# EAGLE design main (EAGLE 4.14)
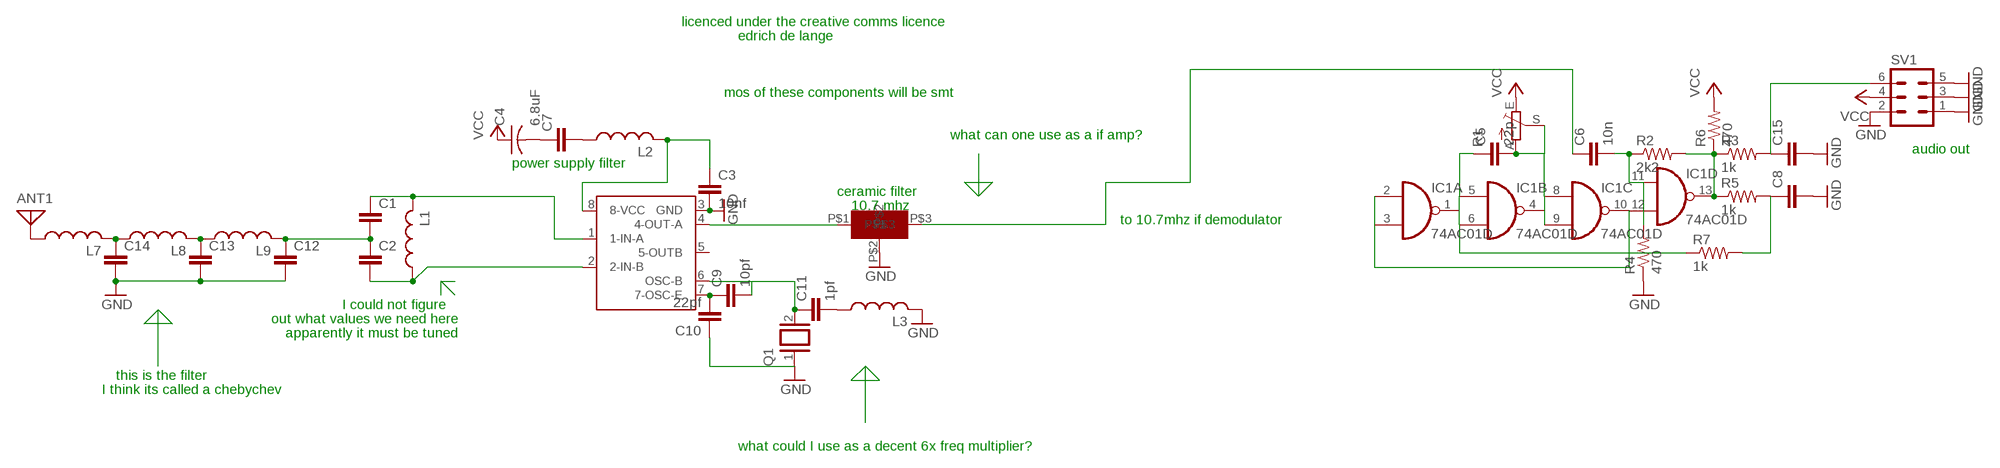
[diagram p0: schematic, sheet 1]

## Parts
ANT1  ANTENNA  [PAD-01]
C1  C-EUC1206K  [C1206K]
C2  C-EUC1206K  [C1206K]
C3  10nf  C-EUC1206K  [C1206K]
C4  6.8uF  CAP-2,5  [C-2,5]
C5  22p  C-EUC1206K  [C1206K]
C6  10n  C-EUC1206K  [C1206K]
C7  C-EU025-025X050  [C025-025X050]
C8  C-EUC1206K  [C1206K]
C9  10pf  C-EUC1206K  [C1206K]
C10  22pf  C-EUC1206  [C1206]
C11  1pf  C-EUC1206K  [C1206K]
C12  C-EUC1206K  [C1206K]
C13  C-EUC1206K  [C1206K]
C14  C-EUC1206K  [C1206K]
C15  C-EUC1206K  [C1206K]
IC1  74AC01D  [SO14]
L1  L-USL3230M  [L3230M]
L2  L-USL3230M  [L3230M]
L3  L-USL3230M  [L3230M]
L7  L-USL3230M  [L3230M]
L8  L-USL3230M  [L3230M]
L9  L-USL3230M  [L3230M]
Q1  XTAL/S  [QS]
R1  TRIM_EU-CA6V  [CA6V]
R2  2k2  R-US_M3216  [M3216]
R3  1k  R-US_M3216  [M3216]
R4  470  R-US_M3216  [M3216]
R5  1k  R-US_M3216  [M3216]
R6  470  R-US_M3216  [M3216]
R7  1k  R-US_M3216  [M3216]
SV1  MA03-2  [MA03-2]
U$1  NE602SMT  [SO-8]
U$2  FILTER  [FILTER]

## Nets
GND: C3.2 C8.2 C10.1 C12.2 C13.2 C14.2 C15.2 L3.2 Q1.1 R4.1 SV1.1 SV1.2 SV1.3 SV1.5 U$1.3(GND) U$2.P$2
N$1: ANT1.1 L7.1
N$2: C1.1 L1.2 U$1.1(1-IN-A)
N$3: C6.1 U$2.P$3
N$4: C14.1 L7.2 L8.1
N$5: C13.1 L8.2 L9.1
N$6: U$1.4(4-OUT-A) U$2.P$1
N$7: C2.2 L1.1 U$1.2(2-IN-B)
N$8: C1.2 C2.1 C12.1 L9.2
N$9: C4.2 C7.1
N$10: C9.2 C11.1 Q1.2 U$1.6(OSC-B)
N$11: C9.1 C10.2 U$1.7(7-OSC-E)
N$12: C7.2 L2.1
N$13: C3.1 L2.2 U$1.8(8-VCC)
N$14: C11.2 L3.1
N$15: C5.1 IC1.1(A:O) IC1.5(B:I0) IC1.6(B:I1) R7.1
N$16: C5.2 IC1.4(B:O) IC1.8(C:I0) IC1.9(C:I1) R1.A R1.S
N$17: IC1.2(A:I0) IC1.3(A:I1) IC1.10(C:O) IC1.12(D:I1)
N$18: C6.2 IC1.11(D:I0) R2.1 R4.2
N$19: IC1.13(D:O) R2.2 R3.1 R5.1 R6.1
N$23: C15.1 R3.2 SV1.6
N$24: C8.1 R5.2 R7.2
VCC: C4.1 R1.E R6.2 SV1.4
Unconnected: U$1.5(5-OUTB)

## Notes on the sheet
- licenced under the creative comms licence
- edrich de lange
- mos of these components will be smt
- what can one use as a if amp?
- audio out
- power supply filter
- ceramic filter
- 10.7 mhz
- to 10.7mhz if demodulator
- I could not figure
- out what values we need here
- apparently it must be tuned
- this is the filter
- I think its called a chebychev
- what could I use as a decent 6x freq multiplier?

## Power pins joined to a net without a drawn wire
GND: IC1.7(P:GND)
VCC: IC1.14(P:VCC)

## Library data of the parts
ANT1 = discrete:ANTENNA
C1-C3 C5-C15 = rcl:C-EU: CAPACITOR, European symbol
C4 = discrete:CAP-2,5
IC1 = 74xx-eu:74*01: Quad 2-input NAND gate, open collector
L1-L3 L7-L9 = rcl:L-US: INDUCTOR, American symbol
Q1 = special:XTAL/S: CRYSTAL
R1 = pot:TRIM_EU-: POTENTIOMETER
R2-R7 = rcl:R-US_: RESISTOR, American symbol
SV1 = con-lstb:MA03-2: PIN HEADER
U$1 = eddeie:NE602
U$2 = eddeie:FILTER

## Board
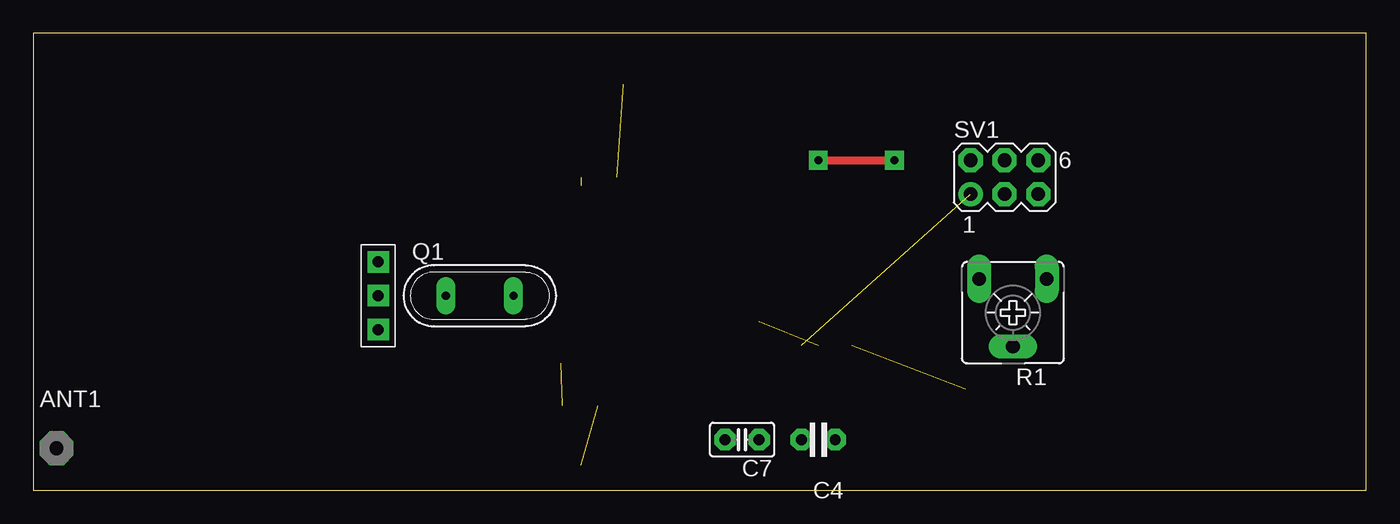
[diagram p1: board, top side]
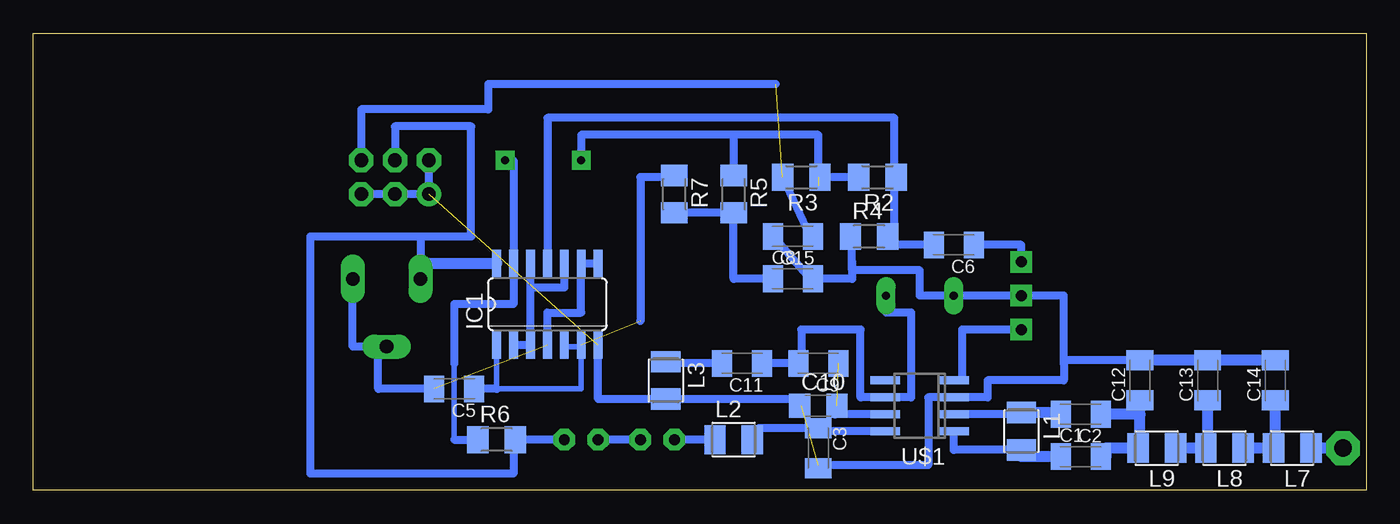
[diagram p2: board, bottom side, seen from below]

Size 100 x 34.28 mm. Coordinates in mm from the lower left corner, seen from the top.
Outline: 0,0 100,0 100,34.28 0,34.28 0,0
Copper layers (1*16): Top 0.035mm / dielectric 1.5mm / Bottom 0.035mm
Design rules "default": minimum track width 0.3mm, minimum drill 0.8mm, track to track 0.3mm, track to pad 0.3mm, pad to pad 0.3mm, via to via 0.3mm, smd to smd 0.5mm, copper to edge 1mm, drill to drill 0.9mm, minimum pad ring 0.4mm, minimum via ring 0.4mm, stop-mask expansion 4mil, vias tented up to drill 0mil, thermal gap 10mil

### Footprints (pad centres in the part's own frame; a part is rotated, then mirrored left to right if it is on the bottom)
PAD-01 = drill 1.321 pad 2.54 octagon: 1 0,0
C1206K = smd 1.5 x 2: 1 -1.5,0; 2 1.5,0
C-2,5 = drill 0.813 pad 1.6 octagon: 1 -1.27,0; 2 1.27,0
C025-025X050 = drill 0.813 octagon: 1 -1.27,0; 2 1.27,0
C1206 = smd 1.6 x 1.8: 1 -1.4,0; 2 1.4,0
SO14 = smd 0.66 x 2.032: 1 -3.81,-3.073; 2 -2.54,-3.073; 3 -1.27,-3.073; 4 0,-3.073; 5 1.27,-3.073; 6 2.54,-3.073; 7 3.81,-3.073; 8 3.81,3.073; 9 2.54,3.073; 10 1.27,3.073; 11 0,3.073; 12 -1.27,3.073; 13 -2.54,3.073; 14 -3.81,3.073
L3230M = smd 1.6 x 2.2: 1 -1.4,0; 2 1.4,0
QS = drill 0.61 long: 1 -2.54,0; 2 2.54,0
CA6V = drill 1.016 long: A -2.54,-2.54; E 2.54,-2.54; S 0,2.54
M3216 = smd 1.6 x 2: 1 -1.4,0; 2 1.4,0
MA03-2 = drill 1.016 round: 1 -2.54,-1.27 | drill 1.016 octagon: 2 -2.54,1.27; 3 0,-1.27; 4 0,1.27; 5 2.54,-1.27; 6 2.54,1.27
SO-8 = smd 0.6 x 2.2: 1 -1.905,-2.6; 2 -0.635,-2.6; 3 0.635,-2.6; 4 1.905,-2.6; 5 1.905,2.6; 6 0.635,2.6; 7 -0.635,2.6; 8 -1.905,2.6
FILTER = drill 0.813 square: P$1 -2.54,0; P$2 0,0; P$3 2.54,0

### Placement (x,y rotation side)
ANT1  1.74,3.17 0 top
C1  21.42,2.54 0 bottom
C2  21.42,5.71 180 bottom
C3  41.11,3.17 270 bottom
C4  58.89,3.8 180 top
C5  68.41,7.62 180 bottom
C6  30.95,18.41 180 bottom
C7  53.17,3.8 180 top
C8  43.02,15.87 0 bottom
C9  41.11,9.52 180 bottom
C10  41.11,6.34 0 bottom
C11  46.82,9.52 180 bottom
C12  16.98,8.25 90 bottom
C13  11.9,8.25 90 bottom
C14  6.82,8.25 90 bottom
C15  43.02,19.04 180 bottom
IC1  61.43,13.97 0 bottom
L1  25.87,4.44 270 bottom
L2  47.46,3.8 0 bottom
L3  52.54,8.25 270 bottom
L7  5.55,3.17 180 bottom
L8  10.63,3.17 180 bottom
L9  15.71,3.17 180 bottom
Q1  33.49,14.6 0 top
R1  73.5,13.33 180 top
R2  36.66,23.49 180 bottom
R3  42.38,23.49 180 bottom
R4  37.3,19.04 0 bottom
R5  47.46,22.22 270 bottom
R6  65.24,3.8 0 bottom
R7  51.91,22.22 270 bottom
SV1  72.86,23.49 0 top
U$1  33.49,6.34 90 bottom
U$2  25.87,14.6 90 top

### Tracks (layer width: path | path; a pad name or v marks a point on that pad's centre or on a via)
GND  (2 unrouted)
  Bottom 0.61: C3.2 41.11,1.9 32.85,1.9 32.85,6.98 U$1.3 28.41,6.98 28.41,8.25 22.7,8.25 22.7,9.52 | 22.7,9.52 22.7,14.6 U$2.P$2 Q1.1 33.49,14.6 33.49,16.5 38.57,16.5 38.57,17.14 | C12.2 22.7,9.75 22.7,9.52 | C10.1 42.38,6.34 42.38,6.85 L3.2 57.62,6.85 IC1.7 | R4.1 38.57,19.04 38.57,17.14 | SV1.5 SV1.3 SV1.1 SV1.2 | 38.57,17.14 38.57,15.87 C8.2 41.74,15.87 C15.2
  Bottom 0.813: C13.2 C12.2 | C13.2 11.9,9.52 | C13.2 C14.2 6.82,9.52
N$1
  Bottom 0.813: 4.28,3.17 L7.1 ANT1.1
N$2
  Bottom 0.61: U$1.1 30.95,4.44 30.95,3.04 L1.2
  Bottom 0.813: 25.87,3.17 L1.2 25.87,2.54 C1.1
N$3
  Bottom 0.61: C6.1 25.87,18.41 U$2.P$3
N$4
  Bottom 0.813: 9.36,3.17 L8.1 L7.2 6.82,3.17 C14.1
N$5
  Bottom 0.813: L9.1 L8.2 11.9,3.17 C13.1
N$6
  Bottom 0.61: U$2.P$1 30.31,12.06 30.31,8.25 U$1.4 30.95,8.25
N$7
  Bottom 0.61: L1.1 25.87,5.71 U$1.2
  Bottom 0.813: C2.2 22.7,5.71 22.7,5.84 L1.1
N$8
  Bottom 0.813: C1.2 19.52,2.54 19.52,3.17 L9.2 16.98,3.17 16.98,5.71 | 16.98,5.71 C2.1 | 16.98,5.71 C12.1
N$9
  Bottom 0.61: C7.1 C4.2
N$10
  Bottom 0.61: Q1.2 36.03,13.33 34.12,13.33 34.12,6.98 U$1.6 37.94,6.98 37.94,12.06 42.38,12.06 42.38,9.52 C9.2 C11.1 45.55,9.52
N$11  (1 unrouted)
  Bottom 0.61: C10.2 39.84,6.34 39.84,5.71 U$1.7
N$12
  Bottom 0.61: L2.1 C7.2
N$13
  Bottom 0.61: U$1.8 41.11,4.44 C3.1 45.55,4.67 45.55,3.8 L2.2
N$14
  Bottom 0.61: L3.1 52.54,9.52 C11.2
N$15  (1 unrouted)
  Bottom 0.406: 58.89,10.79 58.89,7.62 65.24,7.62 IC1.1 | IC1.5 60.16,10.79 58.89,10.79 | 58.89,10.79 IC1.6
  Bottom 0.61: 67.14,7.62 C5.1 65.24,7.62 | R7.1 51.91,23.49 54.45,23.49 54.45,12.7
N$16  (1 unrouted)
  Bottom 0.61: IC1.9 IC1.8 | IC1.4 61.43,13.33 58.89,13.33 IC1.9 | IC1.9 58.89,17.14 | C5.2 74.13,7.62 74.13,10.79 | 74.13,10.79 R1.S | 74.13,10.79 76.03,10.79 R1.A
N$17
  Bottom 0.61: IC1.10 60.16,15.24 62.7,15.24 | 62.7,17.14 IC1.12 62.7,15.24 | IC1.3 IC1.2 | IC1.2 63.97,10.79 | IC1.2 63.97,11.43 | IC1.3 62.7,10.79 | IC1.3 62.7,15.24
N$18
  Bottom 0.61: C6.2 35.39,18.41 35.39,19.04 | R2.1 35.39,23.49 35.39,19.04 | 35.39,19.04 R4.2 | 35.39,19.04 35.39,27.93 61.43,27.93 IC1.11
N$19  (via drill 0.6)  (1 unrouted)
  Top 0.61: v58.89,24.76 v64.61,24.76
  Bottom 0.406: 68.41,9.52 68.41,3.8
  Bottom 0.61: 41.11,23.49 R3.1 R2.2 37.94,23.49 | 47.46,26.66 41.11,26.66 41.11,22.86 | 47.46,26.66 R5.1 | 47.46,26.66 58.89,26.66 v58.89,24.76 | v64.61,24.76 63.97,24.76 IC1.13 63.97,13.97 68.41,13.97 68.41,9.52 | 66.51,3.8 R6.1 68.41,3.8
N$23  (1 unrouted)
  Bottom 0.61: SV1.6 75.4,28.57 65.88,28.57 65.88,30.47 44.28,30.47 | C15.1 41.74,19.04 R3.2
N$24
  Bottom 0.61: R5.2 47.46,20.95 | R5.2 47.46,15.87 C8.1 | R5.2 R7.2 51.91,20.95
VCC
  Bottom 0.61: C4.1 R6.2 63.97,3.8 63.97,1.27 79.21,1.27 79.21,19.04 70.95,19.04 | 70.95,19.04 70.95,17.04 | 70.95,19.04 67.14,19.04 67.14,27.3 72.86,27.3 SV1.4
  Bottom 0.813: IC1.14 70.95,17.04 R1.E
